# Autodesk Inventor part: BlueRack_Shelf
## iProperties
Shininess: 64.0
Length Units: 11272
Angle Units: 11279
Time Units: 11290
Mass Units: 11286
Length Display Precision: 3
Angle Display Precision: 2
Compacted: True
Part Number: BlueRack_Shelf
Document SubType Name: Modeling
Created: 2005-01
Designer: John Blackburn
Manufacturer: Standard
Standards Organization: Custom
Material: Steel, Mild
Density: 0.0
Volumn: 0.0
Area: 0.0
PropertySet Name: Model Information
Control State: 0
Master: False
Checked Out: False
Author: John Blackburn
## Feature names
1. Extrusion1
2. Extrusion2
3. Hole1
4. Hole2
